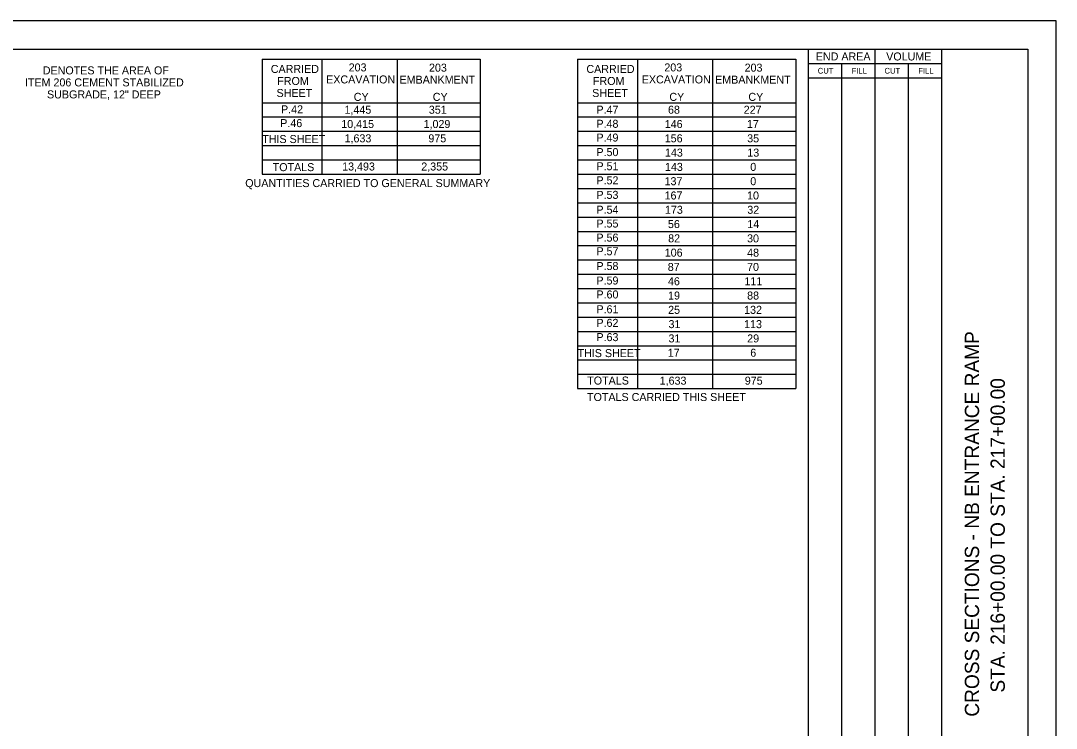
# Model space of a CAD drawing. Extents: x -32 to 34, y 0 to 22.
# Drawn here: x 15.89 to 34, y 9.62 to 22 of the extents above; entities that cross this region are included whole.
import ezdxf

# ---------------------------------------------------------------- set-up
doc = ezdxf.new("R2010")
doc.units = 0
for name, color, linetype in [('SH_Border', 7, 'Continuous'), ('SH_Cut_Line', 7, 'Continuous'), ('SH_Data', 7, 'Continuous'), ('SH_Text', 7, 'Continuous')]:
    doc.layers.add(name, color=color, linetype=linetype)

msp = doc.modelspace()

# ---------------------------------------------------------------- linework, layer by layer
at = {"layer": 'SH_Border'}
msp.add_line((32, 0.5), (32, 21.5), dxfattribs=at)
msp.add_lwpolyline([(1.5, 21.5), (33.5, 21.5), (33.5, 0.5), (1.5, 0.5)], close=True, dxfattribs=at)
at = {"layer": 'SH_Cut_Line'}
msp.add_lwpolyline([(0, 0), (34, 0), (34, 22), (0, 22)], close=True, dxfattribs=at)
at = {"layer": 'SH_Data'}
for p, q in [((29.666, 0.5), (29.666, 21.5)), ((30.833, 0.5), (30.833, 21.5)), ((29.666, 21.25), (32, 21.25)), ((30.25, 1), (30.25, 21.25)), ((31.417, 0.5), (31.417, 21.25)), ((29.666, 21), (32, 21))]:
    msp.add_line(p, q, dxfattribs=at)
at = {"layer": 'SH_Text'}
for p, q in [((20.109, 21.33), (23.924, 21.33)), ((20.109, 21.33), (20.109, 19.316)), ((21.153, 21.33), (21.153, 19.316)), ((22.47, 21.33), (22.47, 19.316)), ((23.924, 21.33), (23.924, 19.316)), ((25.629, 21.33), (29.444, 21.33)), ((25.629, 21.33), (25.629, 15.566)), ((26.674, 21.33), (26.674, 15.566)), ((27.99, 21.33), (27.99, 15.566)), ((29.444, 21.33), (29.444, 15.566)), ((20.109, 20.566), (23.924, 20.566)), ((25.629, 20.566), (29.444, 20.566)), ((20.109, 20.316), (23.924, 20.316)), ((25.629, 20.316), (29.444, 20.316)), ((20.109, 20.066), (23.924, 20.066)), ((25.629, 20.066), (29.444, 20.066)), ((20.109, 19.816), (23.924, 19.816)), ((25.629, 19.816), (29.444, 19.816)), ((20.109, 19.566), (23.924, 19.566)), ((25.629, 19.566), (29.444, 19.566)), ((20.109, 19.316), (23.924, 19.316)), ((25.629, 19.316), (29.444, 19.316)), ((25.629, 19.066), (29.444, 19.066)), ((25.629, 18.816), (29.444, 18.816)), ((25.629, 18.566), (29.444, 18.566)), ((25.629, 18.316), (29.444, 18.316)), ((25.629, 18.066), (29.444, 18.066)), ((25.629, 17.816), (29.444, 17.816)), ((25.629, 17.566), (29.444, 17.566)), ((25.629, 17.316), (29.444, 17.316)), ((25.629, 17.066), (29.444, 17.066)), ((25.629, 16.816), (29.444, 16.816)), ((25.629, 16.566), (29.444, 16.566)), ((25.629, 16.316), (29.444, 16.316)), ((25.629, 16.066), (29.444, 16.066)), ((25.629, 15.816), (29.444, 15.816)), ((25.629, 15.566), (29.444, 15.566))]:
    msp.add_line(p, q, dxfattribs=at)

# ---------------------------------------------------------------- texts
at = {"layer": 'SH_Data'}
for s, height, p in [('END AREA', 0.14, (29.794, 21.305)), ('VOLUME', 0.14, (31.025, 21.305)), ('CUT', 0.1, (29.828, 21.075)), ('FILL', 0.1, (30.42, 21.075)), ('CUT', 0.1, (30.995, 21.075)), ('FILL', 0.1, (31.587, 21.075))]:
    msp.add_text(s, height=height, dxfattribs=at).set_placement(p)
for s, p in [('CROSS SECTIONS - NB ENTRANCE RAMP', (32.65, 9.827)), ('STA. 216+00.00 TO STA. 217+00.00', (33.1, 10.248))]:
    msp.add_text(s, height=0.25, rotation=90, dxfattribs=at).set_placement(p)
at = {"layer": 'SH_Text'}
for s, p in [('DENOTES THE AREA OF', (16.274, 21.061)), ('CARRIED', (20.262, 21.086)), ('203 ', (21.624, 21.113)), ('203', (23.029, 21.109)), ('CARRIED', (25.782, 21.086)), ('203 ', (27.145, 21.113)), ('203', (28.549, 21.109)), ('FROM', (20.375, 20.876)), ('EXCAVATION', (21.23, 20.903)), ('EMBANKMENT', (22.513, 20.899)), ('FROM', (25.896, 20.876)), ('EXCAVATION', (26.75, 20.903)), ('EMBANKMENT', (28.033, 20.899)), ('ITEM 206 CEMENT STABILIZED ', (15.962, 20.851)), ('SUBGRADE, 12" DEEP', (16.348, 20.641)), ('SHEET', (20.363, 20.666)), ('CY', (21.713, 20.598)), ('CY', (23.095, 20.598)), ('SHEET', (25.883, 20.666)), ('CY', (27.233, 20.598)), ('CY', (28.615, 20.598)), ('P.42', (20.441, 20.38)), ('1,445', (21.551, 20.373)), ('351', (23.026, 20.373)), ('P.47', (25.957, 20.374)), ('68', (27.209, 20.373)), ('227', (28.533, 20.373)), ('P.46', (20.427, 20.139)), ('10,415', (21.495, 20.123)), ('1,029', (22.934, 20.123)), ('P.48', (25.957, 20.127)), ('146', (27.152, 20.123)), ('17', (28.589, 20.123)), ('THIS SHEET', (20.112, 19.86)), ('1,633', (21.552, 19.873)), ('975', (23.018, 19.873)), ('P.49', (25.957, 19.886)), ('156', (27.152, 19.873)), ('35', (28.594, 19.873)), ('P.50', (25.957, 19.632)), ('143', (27.156, 19.623)), ('13', (28.596, 19.623)), ('TOTALS', (20.295, 19.369)), ('13,493', (21.51, 19.38)), ('2,355', (22.894, 19.38)), ('P.51', (25.957, 19.385)), ('143', (27.156, 19.373)), ('0', (28.648, 19.373)), ('QUANTITIES CARRIED TO GENERAL SUMMARY', (19.815, 19.09)), ('P.52', (25.957, 19.138)), ('137', (27.149, 19.123)), ('0', (28.648, 19.123)), ('P.53', (25.957, 18.884)), ('167', (27.149, 18.873)), ('10', (28.592, 18.873)), ('P.54', (25.957, 18.624)), ('173', (27.156, 18.623)), ('32', (28.596, 18.623)), ('P.55', (25.957, 18.383)), ('56', (27.208, 18.373)), ('14', (28.596, 18.373)), ('P.56', (25.957, 18.136)), ('82', (27.212, 18.123)), ('30', (28.592, 18.123)), ('P.57', (25.957, 17.898)), ('106', (27.152, 17.873)), ('48', (28.593, 17.873)), ('P.58', (25.957, 17.639)), ('87', (27.205, 17.623)), ('70', (28.592, 17.623)), ('P.59', (25.957, 17.386)), ('46', (27.208, 17.373)), ('111', (28.546, 17.373)), ('P.60', (25.957, 17.142)), ('19', (27.21, 17.123)), ('88', (28.593, 17.123)), ('P.61', (25.957, 16.883)), ('25', (27.211, 16.873)), ('132', (28.54, 16.873)), ('P.62', (25.957, 16.645)), ('31', (27.218, 16.623)), ('113', (28.54, 16.623)), ('P.63', (25.957, 16.396)), ('31', (27.218, 16.373)), ('29', (28.594, 16.373)), ('THIS SHEET', (25.627, 16.116)), ('17', (27.205, 16.123)), ('6', (28.648, 16.123)), ('TOTALS', (25.796, 15.636)), ('1,633', (27.063, 15.634)), ('975', (28.552, 15.634)), ('TOTALS CARRIED THIS SHEET', (25.793, 15.348))]:
    msp.add_text(s, height=0.14, dxfattribs=at).set_placement(p)

doc.saveas('drawing.dxf')
